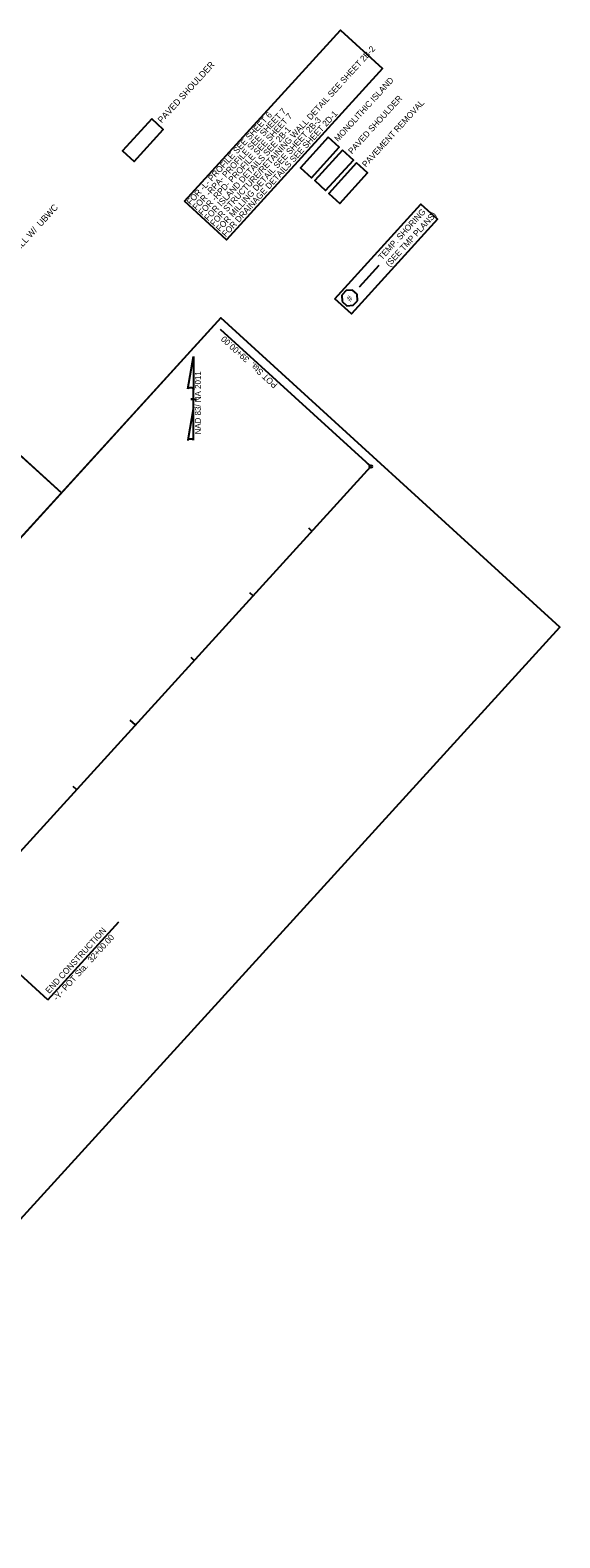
# Model space of a CAD drawing. Extents: x 1807040 to 1808827, y 913493 to 915218.
# Drawn here: x 1808221 to 1808827, y 913493 to 915218 of the extents above; entities that cross this region are included whole.
import ezdxf

# ---------------------------------------------------------------- set-up
doc = ezdxf.new("R2010")
doc.units = 0
for name, color, linetype in [('ENG SEALS CELL', 7, 'Continuous'), ('Old_Level_14', 7, 'Continuous'), ('Old_Level_18', 7, 'Continuous'), ('Old_Level_40', 7, 'Continuous'), ('Prop Horizontal Alignment Station Label', 7, 'Continuous'), ('Prop Horizontal Alignment Tick Large', 7, 'Continuous'), ('Prop Horizontal Alignment Tick Small', 7, 'Continuous'), ('Prop North Arrow NAD83 for Plan Sheets CELL', 7, 'Continuous'), ('Prop Shade Light', 7, 'Continuous'), ('Prop Text', 7, 'Continuous'), ('Scratch_Level_0', 7, 'Continuous'), ('Scratch_Level_1', 7, 'Continuous'), ('Scratch_Level_3', 7, 'Continuous'), ('Temp Shoring', 7, 'Continuous')]:
    doc.layers.add(name, color=color, linetype=linetype)

msp = doc.modelspace()

# ---------------------------------------------------------------- linework, layer by layer
at = {"layer": 'ENG SEALS CELL'}
for points in [[(1808397.1, 915022.1), (1808575.7, 915217.9), (1808623.9, 915174), (1808445.3, 914978.1)], [(1808569.2, 914910.6), (1808667.8, 915018.8), (1808686.9, 915001.5), (1808588.2, 914893.2)]]:
    msp.add_lwpolyline(points, close=True, dxfattribs=at)
at = {"layer": 'Old_Level_14'}
msp.add_line((1807868.2, 915042), (1808256.3, 914688.4), dxfattribs=at)
at = {"layer": 'Old_Level_18'}
msp.add_line((1808438.8, 914888.6), (1807428.3, 913780), dxfattribs=at)
at = {"layer": 'Old_Level_40'}
for points in [[(1808359.8, 915116.4), (1808326.3, 915079.7), (1808339.5, 915067.7), (1808372.9, 915104.4), (1808359.8, 915116.4)], [(1808578, 915080.7), (1808546.2, 915045.8), (1808558.7, 915034.4), (1808590.5, 915069.3), (1808578, 915080.7)]]:
    msp.add_lwpolyline(points, dxfattribs=at)
for points in [[(1808359.8, 915116.4), (1808326.3, 915079.7), (1808339.5, 915067.7), (1808372.9, 915104.4)], [(1808561.8, 915095.5), (1808529.9, 915060.6), (1808542.5, 915049.1), (1808574.3, 915084.1)], [(1808578, 915080.7), (1808546.2, 915045.8), (1808558.7, 915034.4), (1808590.5, 915069.3)], [(1808594.2, 915066), (1808562.4, 915031), (1808574.9, 915019.6), (1808606.8, 915054.6)]]:
    msp.add_lwpolyline(points, close=True, dxfattribs=at)
at = {"layer": 'Prop Horizontal Alignment Station Label'}
for p, q in [((1808609.4, 914719.7), (1808438.4, 914875.5)), ((1808240.7, 914108.6), (1808139, 914201.3)), ((1808240.7, 914108.6), (1808322.1, 914197.9))]:
    msp.add_line(p, q, dxfattribs=at)
msp.add_circle((1808610.5, 914718.7), 1.5, dxfattribs=at)
at = {"layer": 'Prop Horizontal Alignment Tick Large'}
msp.add_line((1808341.1, 914423), (1808335.1, 914428.4), dxfattribs=at)
at = {"layer": 'Prop Horizontal Alignment Tick Small'}
for p, q in [((1808610.5, 914718.7), (1808606.8, 914722)), ((1808543.1, 914644.8), (1808539.4, 914648.1)), ((1808475.8, 914570.8), (1808472.1, 914574.2)), ((1808408.4, 914496.9), (1808404.7, 914500.3)), ((1808273.7, 914349.1), (1808270, 914352.5))]:
    msp.add_line(p, q, dxfattribs=at)
at = {"layer": 'Prop North Arrow NAD83 for Plan Sheets CELL'}
for p, q in [((1808401, 914807.5), (1808407.5, 914844.6)), ((1808401, 914807.5), (1808407.5, 914844.6)), ((1808401, 914807.5), (1808407.5, 914844.6)), ((1808407.6, 914844.6), (1808407.5, 914844.6)), ((1808407.6, 914844.6), (1808407.5, 914844.6)), ((1808407.6, 914844.6), (1808407.5, 914844.6)), ((1808407.6, 914844.6), (1808407.5, 914844.6)), ((1808407.6, 914844.6), (1808407.5, 914844.6)), ((1808407.6, 914844.6), (1808407.5, 914844.6)), ((1808407.6, 914844.6), (1808407.6, 914806.3)), ((1808407.6, 914844.6), (1808407.6, 914806.3)), ((1808407.6, 914844.6), (1808407.6, 914806.3)), ((1808404.4, 914795.8), (1808404.3, 914795.8)), ((1808404.4, 914795.8), (1808404.3, 914795.8)), ((1808404.4, 914795.8), (1808404.3, 914795.8)), ((1808404.4, 914795.8), (1808410.8, 914795.8)), ((1808407.2, 914795.8), (1808404.4, 914795.8)), ((1808404.4, 914795.8), (1808410.8, 914795.8)), ((1808407.2, 914795.8), (1808404.4, 914795.8)), ((1808404.4, 914795.8), (1808410.8, 914795.8)), ((1808407.2, 914795.8), (1808404.4, 914795.8)), ((1808407.6, 914786.5), (1808407.6, 914807.5)), ((1808407.6, 914786.5), (1808407.6, 914807.5)), ((1808407.6, 914786.5), (1808407.6, 914807.5)), ((1808407.6, 914806.3), (1808407.6, 914807.4)), ((1808407.6, 914806.3), (1808407.6, 914807.4)), ((1808407.6, 914806.3), (1808407.6, 914807.4)), ((1808407.6, 914786.5), (1808400.9, 914748.7)), ((1808407.6, 914786.5), (1808400.9, 914748.7)), ((1808407.6, 914786.5), (1808400.9, 914748.7)), ((1808407.6, 914748.9), (1808407.6, 914786.5)), ((1808407.6, 914748.9), (1808407.6, 914786.5)), ((1808407.6, 914748.9), (1808407.6, 914786.5))]:
    msp.add_line(p, q, dxfattribs=at)
for centre, start_param, end_param in [((1808404.3, 914807.1), 0.216388, 2.908219), ((1808404.3, 914807.1), 0.216388, 2.908219), ((1808404.3, 914807.1), 0.216388, 2.908219), ((1808404.3, 914748.6), 0.201328, 3.141593), ((1808404.3, 914748.6), 0.201328, 3.141593), ((1808404.3, 914748.6), 0.201328, 3.141593)]:
    msp.add_ellipse(centre, major_axis=(3.38, -0.02), ratio=0.461098, start_param=start_param, end_param=end_param, dxfattribs=at)
at = {"layer": 'Prop Shade Light'}
for points in [[(1808359.8, 915116.4), (1808326.3, 915079.7), (1808339.5, 915067.7), (1808372.9, 915104.4), (1808359.8, 915116.4)], [(1808578, 915080.7), (1808546.2, 915045.8), (1808558.7, 915034.4), (1808590.5, 915069.3), (1808578, 915080.7)]]:
    msp.add_lwpolyline(points, dxfattribs=at)
for points in [[(1808359.8, 915116.4), (1808326.3, 915079.7), (1808339.5, 915067.7), (1808372.9, 915104.4)], [(1808578, 915080.7), (1808546.2, 915045.8), (1808558.7, 915034.4), (1808590.5, 915069.3)]]:
    msp.add_lwpolyline(points, close=True, dxfattribs=at)
at = {"layer": 'Prop Text'}
for p, q in [((1808582.3, 914920.2), (1808577.4, 914914.9)), ((1808577.4, 914914.9), (1808577.7, 914907.6)), ((1808589.5, 914920.6), (1808582.3, 914920.2)), ((1808594.9, 914915.7), (1808589.5, 914920.6)), ((1808595.2, 914908.4), (1808594.9, 914915.7)), ((1808577.7, 914907.6), (1808583.1, 914902.7)), ((1808583.1, 914902.7), (1808590.3, 914903.1)), ((1808590.3, 914903.1), (1808595.2, 914908.4))]:
    msp.add_line(p, q, dxfattribs=at)
at = {"layer": 'Scratch_Level_0'}
msp.add_lwpolyline([(1808561.8, 915095.5), (1808529.9, 915060.6), (1808542.5, 915049.1), (1808574.3, 915084.1), (1808561.8, 915095.5)], dxfattribs=at)
at = {"layer": 'Scratch_Level_1'}
for points in [[(1807040.3, 914133.7), (1807040.3, 914133.7), (1807428.3, 913780), (1808256.3, 914688.4), (1807868.2, 915042)], [(1807489, 913846.6), (1807877, 913492.9), (1808826.8, 914535), (1808438.8, 914888.6)]]:
    msp.add_lwpolyline(points, close=True, dxfattribs=at)
at = {"layer": 'Scratch_Level_3'}
msp.add_line((1807667.4, 913683.9), (1808610.5, 914718.7), dxfattribs=at)
at = {"layer": 'Temp Shoring'}
msp.add_line((1808597.4, 914924.2), (1808620.1, 914949), dxfattribs=at)

# ---------------------------------------------------------------- texts
at = {"layer": 'Prop Horizontal Alignment Station Label'}
for s, rotation, p in [('POT Sta.  39+00.00', 137.6532, (1808504.3, 914812.7)), ('END CONSTRUCTION', 47.6532, (1808242.4, 914115.1)), ('-Y- POT Sta.  32+00.00', 47.6532, (1808251.3, 914107))]:
    msp.add_text(s, height=7, rotation=rotation, dxfattribs=at).set_placement(p)
at = {"layer": 'Prop North Arrow NAD83 for Plan Sheets CELL'}
msp.add_text('NAD 83/ NA 2011', height=6.8, rotation=90, dxfattribs=at).set_placement((1808416, 914755.4))
msp.add_text('NAD 83/ NA 2011', height=6.8, rotation=90, dxfattribs=at).set_placement((1808416, 914755.4))
msp.add_text('NAD 83/ NA 2011', height=6.8, rotation=90, dxfattribs=at).set_placement((1808416, 914755.4))
at = {"layer": 'Prop Text'}
for s, height, rotation, p in [('FOR STRUCTURE/RETAINING WALL DETAIL SEE SHEET 2B-2', 7, 47.6529, (1808431, 914993)), ('PAVED SHOULDER', 7.35, 47.6532, (1808371.2, 915111)), ('MONOLITHIC ISLAND', 7, 47.6532, (1808573.1, 915089.9)), ('PAVED SHOULDER', 7, 47.6532, (1808588.9, 915075.6)), ('PAVEMENT REMOVAL', 7, 47.6532, (1808604.9, 915060.5)), ('FOR -L- PROFILE SEE SHEET 6', 7, 47.6529, (1808404.1, 915017.5)), ('FOR -RPA- PROFILE SEE SHEET 7', 7, 47.6529, (1808410.8, 915011.4)), ('FOR -RPD- PROFILE SEE SHEET 7', 7, 47.6529, (1808417.5, 915005.3)), ('FOR MILLING DETAIL SEE SHEET 2B-3', 7, 47.6529, (1808437.7, 914986.9)), ('FOR DRAINAGE DETAILS SEE SHEET 2D-1', 7, 47.6529, (1808444.4, 914980.8)), ('FOR ISLAND DETAILS SEE 2B-1', 7, 47.6529, (1808424.2, 914999.1)), ('MILL & FILL W/  UBWC', 7.35, 47.6532, (1808183.3, 914938)), ('TEMP. SHORING', 7, 47.5582, (1808623.3, 914954.4)), ('(SEE TMP PLANS)', 7, 47.5582, (1808631.7, 914946.7)), ('#', 7, 47.6532, (1808586.9, 914906.7))]:
    msp.add_text(s, height=height, rotation=rotation, dxfattribs=at).set_placement(p)

doc.saveas('drawing.dxf')
